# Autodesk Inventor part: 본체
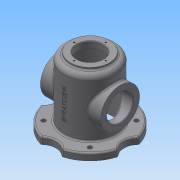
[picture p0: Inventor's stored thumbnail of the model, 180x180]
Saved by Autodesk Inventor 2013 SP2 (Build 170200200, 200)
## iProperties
Created: 2026-07
Part Number: 본체
Material: Generic
Document SubType Name: Modeling
Designer: aa
Density: 1 g/cm^3
Author: aa
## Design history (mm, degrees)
sketch "스케치1"
  geometry: C1 r 82 at (0, 0); 1 further point
  constraints: 1 centre point, 1 coincident
  dimensions: "d0" = 164 diameter of C1
extrude "돌출1" new body sketch "스케치1" distance "d1" = 14; taper "d2" = 0 deg
sketch "스케치2"
  geometry: C1 r 82 at (0, 0) reference; C2 r 30 at (-100, 0); C3 r 30 at (0, -100); C4 r 30 at (100, 0); C5 r 30 at (0, 100)
  constraints: 4 centre point, 1 horizontal alignment, 9 other
  dimensions: "d3" = 60 diameter of C2; "d4" = 100 distance of C1.centre C2.centre; "d7" = 360 deg dimension on C1.centre C2.centre (derived)
extrude "돌출2" cut sketch "스케치2" distance "d9" = 14; taper "d10" = 0 deg
sketch "스케치3"
  geometry: C1 r 53 at (0, 0); A1 r 82 centre (0, 0) between (-21.541, 79.12) and (-79.12, 21.541) reference
  constraints: 1 centre point, 1 coincident
  dimensions: "d11" = 106 diameter of C1
extrude "돌출3" join sketch "스케치3" distance "d12" = 118; taper "d13" = 0 deg
sketch "스케치4"
  geometry: C1 r 53 at (0, 0) reference; C2 r 40 at (0, 0); 1 further point
  constraints: 1 centre point, 1 coincident
  dimensions: "d14" = 80 diameter of C2
extrude "돌출4" join sketch "스케치4" distance "d15" = 5; taper "d16" = 0 deg
sketch "스케치5"
  geometry: C1 r 45 at (0, 0); A1 r 82 centre (0, 0) between (-21.541, 79.12) and (-79.12, 21.541) reference
  constraints: 1 centre point, 1 coincident
  dimensions: "d17" = 90 diameter of C1
extrude "돌출5" cut sketch "스케치5" distance "d18" = 124; taper "d19" = 0 deg
sketch "스케치6"
  geometry: C1 r 40 at (0, 0) reference; C2 r 27 at (0, 0)
  constraints: 1 centre point, 1 coincident
  dimensions: "d20" = 54 diameter of C2
extrude "돌출6" cut sketch "스케치6" stored distance "d21" = 124; taper "d22" = 0 deg
fillet "모깎기1" dims "d23" = 10
fillet "모깎기2" dims "d24" = 3
chamfer "모따기1" distance "d25" = 1; stored, may be unused: second distance "d26" = 2, angle "d27" = 45 deg
sketch "스케치7"
  geometry: C1 r 40 at (0, 0) reference; 1 further point
  constraints: 1 vertical alignment
  dimensions: "d28" = 32.5 distance of C1.centre point (0, 32.5)
hole "구멍1" sketch "스케치7" at (0, 32.5) diameter "d29" = 3.242; stored, may be unused: countersink angle "d33" = 90 deg, drill point angle "d35" = 118 deg; dims "d30" = 8, "d31" = 4, "d32" = 2, "d34" = 10
sketch "스케치8" dims "d40" = 135
  geometry: L1 (0, 100)-(0, -100); L2 (-47.73, 47.73)-(0, 0); A1 r 30 centre (0, 100) between (-21.541, 79.12) and (21.541, 79.12) reference; A2 r 30 centre (0, -100) between (21.541, -79.12) and (-21.541, -79.12) reference; A3 r 82 centre (0, 0) between (79.12, 21.541) and (21.541, 79.12) reference; 1 further point
  constraints: 4 end point, 1 midpoint, 1 point on line, 1 vertical, 3 other
  dimensions: "d39" = 45 deg angle of L2 L1
hole "구멍2" sketch "스케치8" at (-47.73, 47.73) diameter "d41" = 9; stored, may be unused: countersink angle "d45" = 90 deg, drill point angle "d47" = 118 deg; dims "d42" = 8, "d43" = 4, "d44" = 2, "d46" = 10
node "작업 평면1"
sketch "스케치9"
  geometry: L1 (21.541, 0)-(-21.541, 0) reference; C1 r 40 at (0, 68); 2 further points
  constraints: 1 centre point, 1 midpoint, 1 vertical alignment
  dimensions: "d52" = 80 diameter of C1; "d53" = 68 distance from line of C1.centre L1
extrude "돌출7" join sketch "스케치9" stored distance "d54" = 124; taper "d55" = 0 deg
sketch "스케치10"
  geometry: C1 r 40 at (0, 0) reference; C2 r 27 at (0, 0); 1 further point
  constraints: 1 centre point, 1 coincident
  dimensions: "d57" = 54 diameter of C2
extrude "돌출8" cut sketch "스케치10" distance "d58" = 124; taper "d59" = 0 deg
fillet "모깎기3" dims "d60" = 3
sketch "스케치11"
  geometry: C1 r 27 at (0, 0) reference; 2 further points
  constraints: 1 horizontal alignment
  dimensions: "d61" = 32.5 distance of C1.centre point (-32.5, 0)
hole "구멍3" sketch "스케치11" at (-32.5, 0) diameter "d62" = 3.242; stored, may be unused: countersink angle "d66" = 90 deg, drill point angle "d68" = 118 deg; dims "d63" = 8, "d64" = 4, "d65" = 2, "d67" = 10
fillet "모깎기4" dims "d72" = 3
chamfer "모따기2" distance "d73" = 1; stored, may be unused: second distance "d74" = 2, angle "d75" = 45 deg
fillet "모깎기5" dims "d76" = 3
node "작업 평면2"
sketch "스케치14"
  geometry: L1 (20.357, 0)-(-20.357, 0) reference; 3 further points
  constraints: 1 midpoint, 1 vertical alignment, 1 other
  dimensions: "d79" = 70 distance from line of point (0, 70) L1
feature "엠보싱1" sketch "스케치14" dims "d1" = 14, "d80" = 0.5, "d81" = 0
node "솔리드1"
pattern_circular "원형 패턴1" dims angle "d37" = 360 deg
pattern_circular "원형 패턴2" dims angle "d49" = 360 deg
mirror "대칭1"
pattern_circular "원형 패턴3" dims angle "d70" = 360 deg
mirror "대칭2"
other parameters: "d51" = 62, "d77" = 53.5
